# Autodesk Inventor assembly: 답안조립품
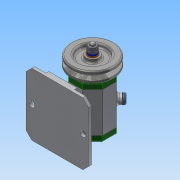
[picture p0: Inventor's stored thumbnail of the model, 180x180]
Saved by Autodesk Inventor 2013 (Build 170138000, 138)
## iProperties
Created: 2018-06
Part Number: 답안조립품
Document SubType Name: Assembly
Designer: Administrator
Author: Administrator
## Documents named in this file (16)
- C:\Users\Administrator\Desktop\480608V1013\답안조립품.iam
- C:\Users\Administrator\Desktop\480608V1013\V벨트풀리.ipt
- C:\Users\Administrator\Desktop\480608V1013\고무캡.ipt
- C:\Users\Administrator\Desktop\480608V1013\너트 M8.ipt
- 너트 M8.ipt
- C:\Users\Administrator\Desktop\480608V1013\뒤커버.ipt
- C:\Users\Administrator\Desktop\480608V1013\베어링 15x32x9.ipt
- C:\Users\Administrator\Desktop\480608V1013\본체.ipt
- C:\Users\Administrator\Desktop\480608V1013\볼트 M4x12.ipt
- C:\Users\Administrator\Desktop\480608V1013\스프링와셔 8.ipt
- C:\Users\Administrator\Desktop\480608V1013\앞커버.ipt
- C:\Users\Administrator\Desktop\480608V1013\오일 실 15 25 7.ipt
- C:\Users\Administrator\Desktop\480608V1013\와셔 8x17.ipt
- C:\Users\Administrator\Desktop\480608V1013\축.ipt
- C:\Users\Administrator\Desktop\480608V1013\키 3x3x12.ipt
- 키 3x3x12.ipt
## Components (2 placed, 2 different names)
1. V벨트풀리:1
2. 고무캡:1
